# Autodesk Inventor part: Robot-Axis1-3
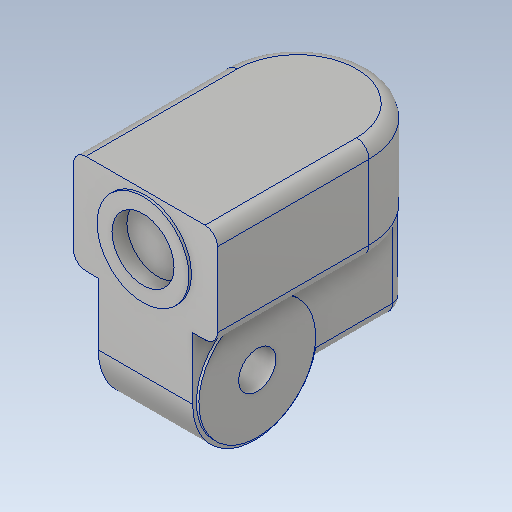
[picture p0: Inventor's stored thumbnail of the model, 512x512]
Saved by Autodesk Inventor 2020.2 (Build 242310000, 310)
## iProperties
Created: 2018-07
Part Number: Robot-Axis1-3
Material: Aluminum 6061
Description: 123456
Document SubType Name: Modeling
Designer: Power User
Mass: 6944.94 g
Surface Area: 1273.07 cm^2
Volume: 2572.2 cm^3
Density: 2.7 g/cm^3
Appearance: Aluminum - Flat
Title: GEAR
Author: Power User
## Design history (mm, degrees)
sketch "Sketch6" dims "d50" = 100
  geometry: L1 (-58, 150)-(58, 150); L2 (58, 150)-(58, 70); L3 (58, 70)-(-58, 70); L4 (-58, 70)-(-58, 150); L5 (-58, 150)-(58, 70); L6 (58, 150)-(-58, 70); L7 (-38, 20)-(38, 20); L8 (38, 20)-(38, 70); L9 (38, 70)-(-38, 70); L10 (-38, 70)-(-38, 20); L11 (-38, 20)-(38, 70); L12 (38, 20)-(-38, 70); 8 further points
  constraints: 24 end point, 8 midpoint, 3 parallel, 2 perpendicular, 2 vertical alignment, 1 coincident, 1 collinear, 1 horizontal
  dimensions: "d44" = 116 distance of L2.end L3.end; "d45" = 80 distance of L1.end L2.end; "d47" = 76 distance of L7.start L7.end; "d54" = 130 distance between parallel lines of L1 L7; "d55" = 150 distance from line of L1 point (0, 0)
extrude "Extrusion5" new body sketch "Sketch6" distance "d48" = 180; taper "d49" = 0 deg
sketch "Sketch7"
  geometry: L1 (20, -180)-(20, 0) reference; L2 (20, 0)-(150, 0) reference; L3 (150, 0)-(150, -180) reference; L4 (150, -180)-(20, -180) reference; C1 r 50 at (20, -50); C2 r 47 at (20, -50)
  constraints: 2 centre point, 1 coincident, 1 tangent
  dimensions: "d50" = 100 diameter of C1; "d51" = 130 distance from line of C1.centre L3; "d74" = 94 diameter of C2
  node "Project Cut Edges2"
extrude "Extrusion6" join sketch "Sketch7" stored distance "d52" = 76; taper "d53" = 0 deg
extrude "Extrusion9" join sketch "Sketch7" stored distance "d75" = 80; taper "d76" = 0 deg
sketch "Sketch11"
  geometry: C1 r 47 at (0, 0) reference; 2 further points
  constraints: 1 coincident
hole "Hole3" sketch "Sketch11" at (0, 0) diameter "d78" = 30; stored, may be unused: countersink angle "d82" = 90 deg, drill point angle "d84" = 118 deg; dims "d79" = 6, "d80" = 4, "d81" = 2, "d83" = 8
node "Direct Edit1"
sketch "Sketch8"
  geometry: L1 (58, 150)-(58, 70) reference; C1 r 25 at (0, 110); C2 r 37 at (0, 110); 2 further points
  constraints: 2 centre point, 1 coincident, 1 horizontal alignment, 1 midpoint, 1 vertical alignment
  dimensions: "d59" = 50 diameter of C1; "d60" = 74 diameter of C2
extrude "Extrusion7" join sketch "Sketch8" distance "d62" = 2; taper "d63" = 0 deg
sketch "Sketch9"
  geometry: C1 r 25 at (0, 0) reference; 1 further point
extrude "Extrusion8" cut sketch "Sketch9" distance "d64" = 10; taper "d65" = 0 deg
fillet "Fillet2"
fillet "Fillet3" dims "d73" = 10
body "Solid2"
node "Projected Loop1"
move_body "Move1" dims "d58" = 20
other parameters: "d56" = 0, "d57" = 0
